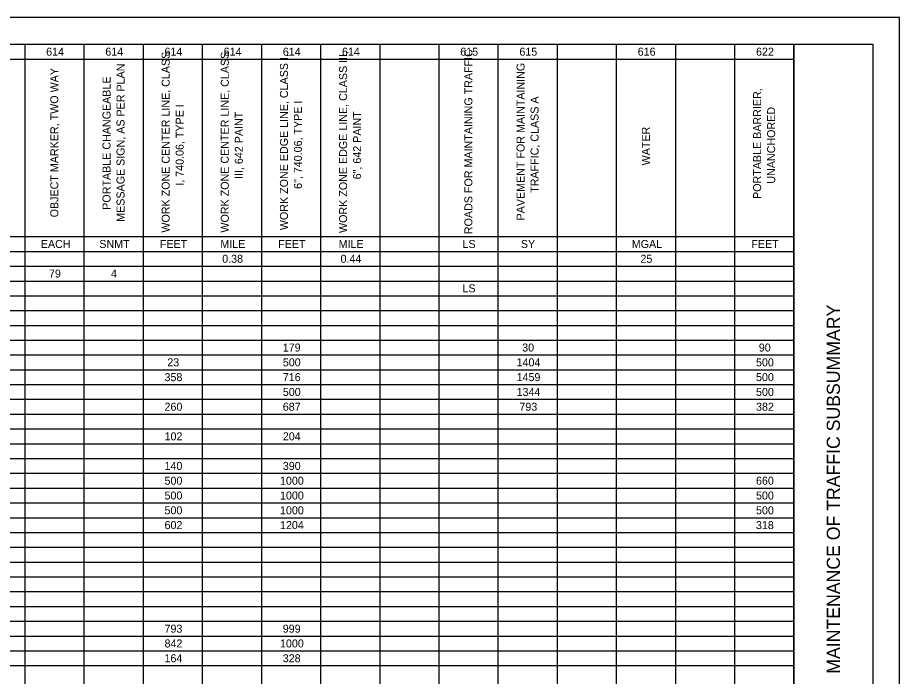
# Model space of a CAD drawing. Extents: x 0 to 34, y 0 to 22.
# Drawn here: x 17.31 to 34, y 9.53 to 22 of the extents above; entities that cross this region are included whole.
import ezdxf

# ---------------------------------------------------------------- set-up
doc = ezdxf.new("R2010")
doc.units = 0
for name, color, linetype in [('Default', 7, 'Continuous'), ('SH_Border', 7, 'Continuous'), ('SH_Cut_Line', 7, 'Continuous'), ('SH_Data', 7, 'Continuous')]:
    doc.layers.add(name, color=color, linetype=linetype)

msp = doc.modelspace()

# ---------------------------------------------------------------- linework, layer by layer
at = {"layer": 'Default'}
for p, q in [((1.5, 21.496), (32, 21.496)), ((17.442, 21.496), (17.442, 0.498)), ((18.562, 21.496), (18.562, 0.498)), ((19.681, 21.496), (19.681, 0.498)), ((20.801, 21.496), (20.801, 0.498)), ((21.921, 21.496), (21.921, 0.498)), ((23.041, 21.496), (23.041, 0.498)), ((24.161, 21.496), (24.161, 0.498)), ((25.281, 21.496), (25.281, 0.498)), ((26.401, 21.496), (26.401, 0.498)), ((27.521, 21.496), (27.521, 0.498)), ((28.64, 21.496), (28.64, 0.498)), ((29.76, 21.496), (29.76, 0.498)), ((30.88, 21.496), (30.88, 0.498)), ((32, 21.496), (32, 0.498)), ((5.123, 21.216), (32, 21.216)), ((5.123, 17.856), (32, 17.856)), ((1.5, 17.576), (32, 17.576)), ((1.5, 17.296), (32, 17.296)), ((1.5, 17.016), (32, 17.016)), ((1.5, 16.736), (32, 16.736)), ((1.5, 16.456), (32, 16.456)), ((1.5, 16.176), (32, 16.176)), ((1.5, 15.897), (32, 15.897)), ((1.5, 15.617), (32, 15.617)), ((1.5, 15.337), (32, 15.337)), ((1.5, 15.057), (32, 15.057)), ((1.5, 14.777), (32, 14.777)), ((1.5, 14.497), (32, 14.497)), ((1.5, 14.217), (32, 14.217)), ((1.5, 13.937), (32, 13.937)), ((1.5, 13.657), (32, 13.657)), ((1.5, 13.377), (32, 13.377)), ((1.5, 13.097), (32, 13.097)), ((1.5, 12.817), (32, 12.817)), ((1.5, 12.537), (32, 12.537)), ((1.5, 12.257), (32, 12.257)), ((1.5, 11.977), (32, 11.977)), ((1.5, 11.697), (32, 11.697)), ((1.5, 11.417), (32, 11.417)), ((1.5, 11.137), (32, 11.137)), ((1.5, 10.857), (32, 10.857)), ((1.5, 10.577), (32, 10.577)), ((1.5, 10.297), (32, 10.297)), ((1.5, 10.017), (32, 10.017)), ((1.5, 9.737), (32, 9.737))]:
    msp.add_line(p, q, dxfattribs=at)
at = {"layer": 'SH_Border'}
msp.add_line((32, 0.5), (32, 21.5), dxfattribs=at)
msp.add_lwpolyline([(1.5, 21.5), (33.5, 21.5), (33.5, 0.5), (1.5, 0.5)], close=True, dxfattribs=at)
at = {"layer": 'SH_Cut_Line'}
msp.add_lwpolyline([(0, 0), (34, 0), (34, 22), (0, 22)], close=True, dxfattribs=at)

# ---------------------------------------------------------------- texts
at = {"layer": 'Default'}
for s, height, p in [('614', 0.1515, (17.847, 21.28)), ('614', 0.1515, (18.967, 21.28)), ('614', 0.1515, (20.087, 21.28)), ('614', 0.1515, (21.207, 21.28)), ('614', 0.1515, (22.327, 21.28)), ('614', 0.1515, (23.447, 21.28)), ('615', 0.1515, (25.686, 21.28)), ('615', 0.1515, (26.806, 21.28)), ('616', 0.1515, (29.046, 21.28)), ('622', 0.1515, (31.286, 21.28)), ('EACH', 0.1515, (17.745, 17.641)), ('SNMT', 0.1515, (18.853, 17.641)), ('FEET', 0.1515, (20, 17.641)), ('MILE', 0.1515, (21.144, 17.641)), ('FEET', 0.1515, (22.24, 17.641)), ('MILE', 0.1515, (23.384, 17.641)), ('LS', 0.1515, (25.729, 17.641)), ('SY', 0.1515, (26.834, 17.641)), ('MGAL', 0.1515, (28.934, 17.641)), ('FEET', 0.1515, (31.198, 17.641)), ('0.38', 0.1515, (21.18, 17.361)), ('0.44', 0.1515, (23.42, 17.361)), ('25', 0.1515, (29.098, 17.361)), ('79', 0.1515, (17.9, 17.081)), ('4', 0.152, (19.073, 17.081)), ('LS', 0.1515, (25.729, 16.801)), ('179', 0.1515, (22.326, 15.681)), ('30', 0.1515, (26.859, 15.681)), ('90', 0.1515, (31.339, 15.681)), ('23', 0.1515, (20.14, 15.401)), ('500', 0.1515, (22.327, 15.401)), ('1404', 0.1515, (26.753, 15.401)), ('500', 0.1515, (31.286, 15.401)), ('358', 0.1515, (20.087, 15.121)), ('716', 0.1515, (22.327, 15.121)), ('1459', 0.1515, (26.753, 15.121)), ('500', 0.1515, (31.286, 15.121)), ('500', 0.1515, (22.327, 14.841)), ('1344', 0.1515, (26.753, 14.841)), ('500', 0.1515, (31.286, 14.841)), ('260', 0.1515, (20.087, 14.561)), ('687', 0.1515, (22.327, 14.561)), ('793', 0.1515, (26.806, 14.561)), ('382', 0.1515, (31.286, 14.561)), ('102', 0.1515, (20.088, 14.001)), ('204', 0.1515, (22.327, 14.001)), ('140', 0.1515, (20.087, 13.441)), ('390', 0.1515, (22.327, 13.441)), ('500', 0.1515, (20.087, 13.161)), ('1000', 0.1515, (22.274, 13.161)), ('660', 0.1515, (31.286, 13.161)), ('500', 0.1515, (20.087, 12.881)), ('1000', 0.1515, (22.274, 12.881)), ('500', 0.1515, (31.286, 12.881)), ('500', 0.1515, (20.087, 12.601)), ('1000', 0.1515, (22.274, 12.601)), ('500', 0.1515, (31.286, 12.601)), ('602', 0.1515, (20.088, 12.321)), ('1204', 0.1515, (22.274, 12.321)), ('318', 0.1515, (31.285, 12.321)), ('793', 0.1515, (20.087, 10.361)), ('999', 0.1515, (22.326, 10.361)), ('842', 0.1515, (20.088, 10.081)), ('1000', 0.1515, (22.274, 10.081)), ('164', 0.1515, (20.087, 9.801)), ('328', 0.1515, (22.326, 9.801))]:
    msp.add_text(s, height=height, dxfattribs=at).set_placement(p)
for s, height, p in [('ROADS FOR MAINTAINING TRAFFIC', 0.15151, (25.916, 17.903)), ('WORK ZONE CENTER LINE, CLASS ', 0.15151, (20.185, 17.932)), ('WORK ZONE CENTER LINE, CLASS ', 0.15151, (21.304, 17.932)), ('WORK ZONE EDGE LINE, CLASS I, ', 0.15151, (22.424, 17.978)), ('WORK ZONE EDGE LINE, CLASS III, ', 0.15151, (23.544, 17.925)), ('OBJECT MARKER, TWO WAY', 0.15151, (18.077, 18.221)), ('MESSAGE SIGN, AS PER PLAN', 0.15151, (19.33, 18.136)), ('PAVEMENT FOR MAINTAINING ', 0.15151, (26.904, 18.162)), ('PORTABLE CHANGEABLE ', 0.15151, (19.065, 18.364)), ('PORTABLE BARRIER, ', 0.15151, (31.383, 18.569)), ('6", 740.06, TYPE I', 0.15151, (22.689, 18.759)), ('TRAFFIC, CLASS A', 0.15151, (27.169, 18.684)), ('I, 740.06, TYPE I', 0.15151, (20.45, 18.819)), ('III, 642 PAINT', 0.15151, (21.57, 18.947)), ('6", 642 PAINT', 0.15151, (23.809, 18.94)), ('UNANCHORED', 0.1515, (31.648, 18.858)), ('WATER', 0.1515, (29.276, 19.204))]:
    msp.add_text(s, height=height, rotation=90, dxfattribs=at).set_placement(p)
at = {"layer": 'SH_Data'}
msp.add_text('MAINTENANCE OF TRAFFIC SUBSUMMARY', height=0.25, rotation=90, dxfattribs=at).set_placement((32.875, 9.584))

doc.saveas('drawing.dxf')
